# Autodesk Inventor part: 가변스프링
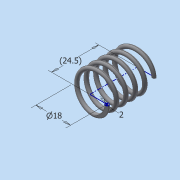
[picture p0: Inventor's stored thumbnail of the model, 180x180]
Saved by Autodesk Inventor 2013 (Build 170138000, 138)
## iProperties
Created: 2017-12
Part Number: 가변스프링
Material: 일반
Document SubType Name: Modeling
Designer: dgall
Density: 1 g/cm^3
Author: dgall
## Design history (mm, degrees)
sketch "스케치1"
  geometry: L1 (9, 0)-(0, 0); L2 (0, 0)-(0, 24.5); L3 (0, 24.5)-(9, 24.5); C1 r 1 at (9, 0)
  constraints: 6 end point, 2 parallel, 1 centre point, 1 coincident, 1 horizontal, 1 perpendicular
  dimensions: "d0" = 18 diameter of L1.start L2; "d2" = 24.5 distance of L1.end L2.end (derived); "d3" = 2 diameter of C1
feature "코일1" pitch "d4" = 10; turns "d6" = 5; dims "d5" = 24.5 (= d2), "d7" = 0, angle "d8" = 90 deg, angle "d9" = 90 deg, "d10" = 0, "d11" = 0
node "작업 평면1"
feature "분할1"
node "작업 평면2"
feature "분할2"
node "솔리드1"
other parameters: "d12" = 0, "d13" = 0
